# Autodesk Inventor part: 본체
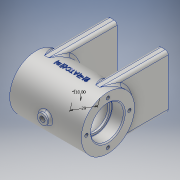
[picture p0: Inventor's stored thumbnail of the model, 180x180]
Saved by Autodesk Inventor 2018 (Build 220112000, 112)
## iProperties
Created: 2020-07
Part Number: 본체
Material: 알루미늄 6061
Document SubType Name: Modeling
Designer: home
Density: 2.7 g/cm^3
Appearance: 알루미늄 - 평지
Mass: 309.62 g
Surface Area: 371.462 cm^2
Volume: 114.674 cm^3
Author: home
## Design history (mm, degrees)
sketch "스케치1"
  geometry: L1 (26.26, 0)-(-26.26, 0); L2 (49.265, -16)-(37.265, -16); L3 (37.265, -16)-(37.265, -14); L4 (37.265, -14)-(35.265, -14); L5 (35.265, -14)-(35.265, -21); L6 (35.265, -21)-(-6.735, -21); L7 (-6.735, -21)-(-6.735, -14); L8 (-6.735, -14)-(-8.735, -14); L9 (-8.735, -14)-(-8.735, -16); L10 (-8.735, -16)-(-20.735, -16); L11 (-20.735, -16)-(-20.735, -26); L12 (-20.735, -26)-(49.265, -26); L13 (49.265, -26)-(49.265, -16); 2 further points
  constraints: 26 end point, 11 perpendicular, 2 horizontal, 1 coincident, 1 midpoint
  dimensions: "d0" = 32 diameter of L2 L1; "d1" = 2 distance between parallel lines of L5 L3; "d2" = 42 diameter of L6 L1; "d3" = 2 distance between parallel lines of L9 L7; "d4" = 32 diameter of L10 L1; "d5" = 52 diameter of L12 L1; "d6" = 70 distance between parallel lines of L11 L13; "d7" = 12 distance of L2.start L2.end; "d8" = 12 distance of L9.end L10.end; "d11" = 49.26497 distance from line of point (0, 0) L13; "d12" = 23.00528 distance from line of L1.start L13; "d88" = 28 diameter of L8 L1; "d89" = 28 diameter of L4 L1
revolve "회전1" sketch "스케치1" stored, may be unused: angle "d13" = 90 deg
node "작업 평면1"
sketch "스케치3"
  geometry: L1 (-20.735, 26)-(-20.735, -26) reference; L2 (-20.735, 26)-(-15.735, 26); L3 (49.265, 26)-(-20.735, 26) reference; L4 (49.265, 26)-(44.265, 26); L5 (44.265, 26)-(44.265, -26); L6 (44.265, -26)-(34.265, -26); L7 (34.265, -26)-(34.265, 26); L8 (-15.735, 26)-(-15.735, -26); L9 (-15.735, -26)-(-5.735, -26); L10 (-5.735, -26)-(-5.735, 26); 1 further point
  constraints: 16 end point, 5 perpendicular, 4 point on line
  dimensions: "d15" = 5 distance of L1.start L2.end; "d16" = 5 distance of L3.start L4.end; "d17" = 52 distance of L4.end L5.end; "d18" = 10 distance of L5.end L6.end; "d19" = 52 distance of L6.end L7.end; "d20" = 52 distance of L2.end L8.end; "d21" = 10 distance of L8.end L9.end
extrude "돌출1" join sketch "스케치3" stored distance "d22" = 10; taper "d23" = 0 deg
node "작업 평면2"
sketch "스케치4"
  geometry: L1 (-20.735, 26)-(-20.735, -26) reference; L2 (-20.735, 0)-(14.265, 0); C1 r 5 at (14.265, 0); 1 further point
  constraints: 2 end point, 1 centre point, 1 coincident, 1 horizontal, 1 midpoint
  dimensions: "d25" = 35 distance of L2.start L2.end; "d26" = 10 diameter of C1
extrude "돌출2" join sketch "스케치4" stored distance "d27" = 10; taper "d28" = 0 deg
sketch "스케치5"
  geometry: C1 r 5 at (14.265, 0) reference; 1 further point
hole "구멍1" sketch "스케치5" at (14.265, 0) diameter "d29" = 5.188; stored, may be unused: countersink angle "d33" = 90 deg, drill point angle "d35" = 118 deg; dims "d30" = 19, "d31" = 4, "d32" = 2, "d34" = 20
node "작업 평면3"
sketch "스케치6"
  geometry: L1 (0, 0)-(-9.919, 27.251); L2 (0, 0)-(29, 0)
  constraints: 4 end point, 1 equal length, 1 horizontal
  dimensions: "d36" = 29 distance of L1.start L1.end; "d37" = 110 deg angle of L2 L1
node "작업 평면4"
sketch "스케치7"
  geometry: C1 r 6 at (0, 0); 2 further points; 1 other entity
  constraints: 1 centre point, 1 other
  dimensions: "d38" = 12 diameter of C1; "d39" = 14.26497 distance of C1.centre point (-14.265, 0); "d40" = 9.91858 distance of point (0, -9.919) C1.centre
extrude "돌출3" join sketch "스케치7" stored distance "d41" = 10; taper "d42" = 0 deg
sketch "스케치8"
  geometry: C1 r 6 at (0, 0) reference; 2 further points
  constraints: 1 coincident
hole "구멍2" sketch "스케치8" at (0, 0) diameter "d43" = 5.188; stored, may be unused: countersink angle "d47" = 90 deg, drill point angle "d49" = 118 deg; dims "d44" = 12, "d45" = 4, "d46" = 2, "d48" = 16
sketch "스케치10"
  geometry: L1 (-49.265, -26)-(-49.265, 26) reference; L2 (-49.265, -26)-(-39.265, -26); L3 (-44.265, -26)-(-34.265, -26) reference; L4 (-39.265, -26)-(-39.265, -20); L5 (-39.265, -20)-(-39.265, 20); L6 (20.735, -26)-(20.735, 26) reference; L7 (20.735, -26)-(10.735, -26); L8 (5.735, -26)-(15.735, -26) reference; L9 (10.735, -26)-(10.735, -20); L10 (10.735, -20)-(10.735, 20); 3 further points
  constraints: 12 end point, 4 coincident, 4 vertical, 2 midpoint
  dimensions: "d50" = 10 distance of L1.start L2.end (derived); "d51" = 6 distance of L2.end L4.end; "d52" = 40 distance of L5.start L5.end; "d53" = 10 distance of L6.start L7.end (derived); "d54" = 6 distance of L7.end L9.end; "d55" = 40 distance of L10.start L10.end
hole "구멍3" sketch "스케치10" at (-39.265, 20), (-39.265, -20), (10.735, 20), (10.735, -20) diameter "d56" = 4.134; stored, may be unused: countersink angle "d60" = 90 deg, drill point angle "d62" = 118 deg; dims "d57" = 8, "d58" = 4, "d59" = 2, "d61" = 10
fillet "모깎기1" dims "d63" = 2, "d64" = 0.3, "d65" = 3, "d66" = 3
sketch "스케치11"
  geometry: A1 r 21 centre (0, 0) between (0, -21) and (-21, 0); 3 further points
  constraints: 4 point on circle, 1 centre point, 1 coincident
  dimensions: "d67" = 42 diameter of A1; "d68" = 29.69848 distance of point (21, 0) point (0, 21); "d69" = 29.69848 distance of point (21, 0) A1.start; "d70" = 42 distance of point (21, 0) A1.end; "d71" = 21 horizontal distance of A1.end A1.start
hole "구멍4" sketch "스케치11" at (0, -21), (-21, 0), (0, 21), (21, 0) diameter "d72" = 3.242; stored, may be unused: countersink angle "d76" = 90 deg, drill point angle "d78" = 118 deg; dims "d73" = 8, "d74" = 4, "d75" = 2, "d77" = 10
chamfer "모따기1" distance "d79" = 1; stored, may be unused: second distance "d80" = 2, angle "d81" = 45 deg
node "작업 평면5"
sketch "스케치12"
  geometry: L1 (20.735, -26)-(20.735, 26) reference; L2 (20.735, -26)-(-4.406, -26); L3 (-49.265, -26)-(20.735, -26) reference; 2 further points
  constraints: 2 end point, 1 point on line, 1 other
  dimensions: "d83" = 35 distance from line of L1 point (-14.265, 0); "d84" = 26 distance from line of point (-14.265, 0) L2; "d85" = 25.14117 distance from line of L2.end L1
feature "엠보싱1" sketch "스케치12" dims "d0" = 32, "d1" = 2, "d2" = 42, "d3" = 2, "d4" = 32, "d5" = 52, "d6" = 70, "d7" = 12, "d8" = 12, "d11" = 49.26497, "d12" = 23.00528, "d15" = 5, "d20" = 52, "d21" = 10, "d86" = 0.5, "d87" = 0, "d88" = 28, "d89" = 28
node "솔리드1"
mirror "미러1"
other parameters: "d14" = 64, "d24" = -29, "d82" = 26
